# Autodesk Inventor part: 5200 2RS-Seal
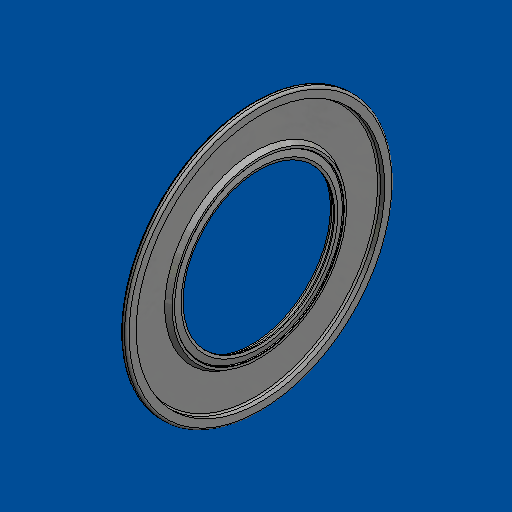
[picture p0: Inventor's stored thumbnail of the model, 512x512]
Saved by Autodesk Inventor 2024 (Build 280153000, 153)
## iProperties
Part Number: 5200 2RS-Seal
Material: Generic
Document SubType Name: Modeling
Designer: amoles
Appearance: Default
Author: amoles
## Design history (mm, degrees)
feature "5200 2RS-Seal"
body "Solid1"
